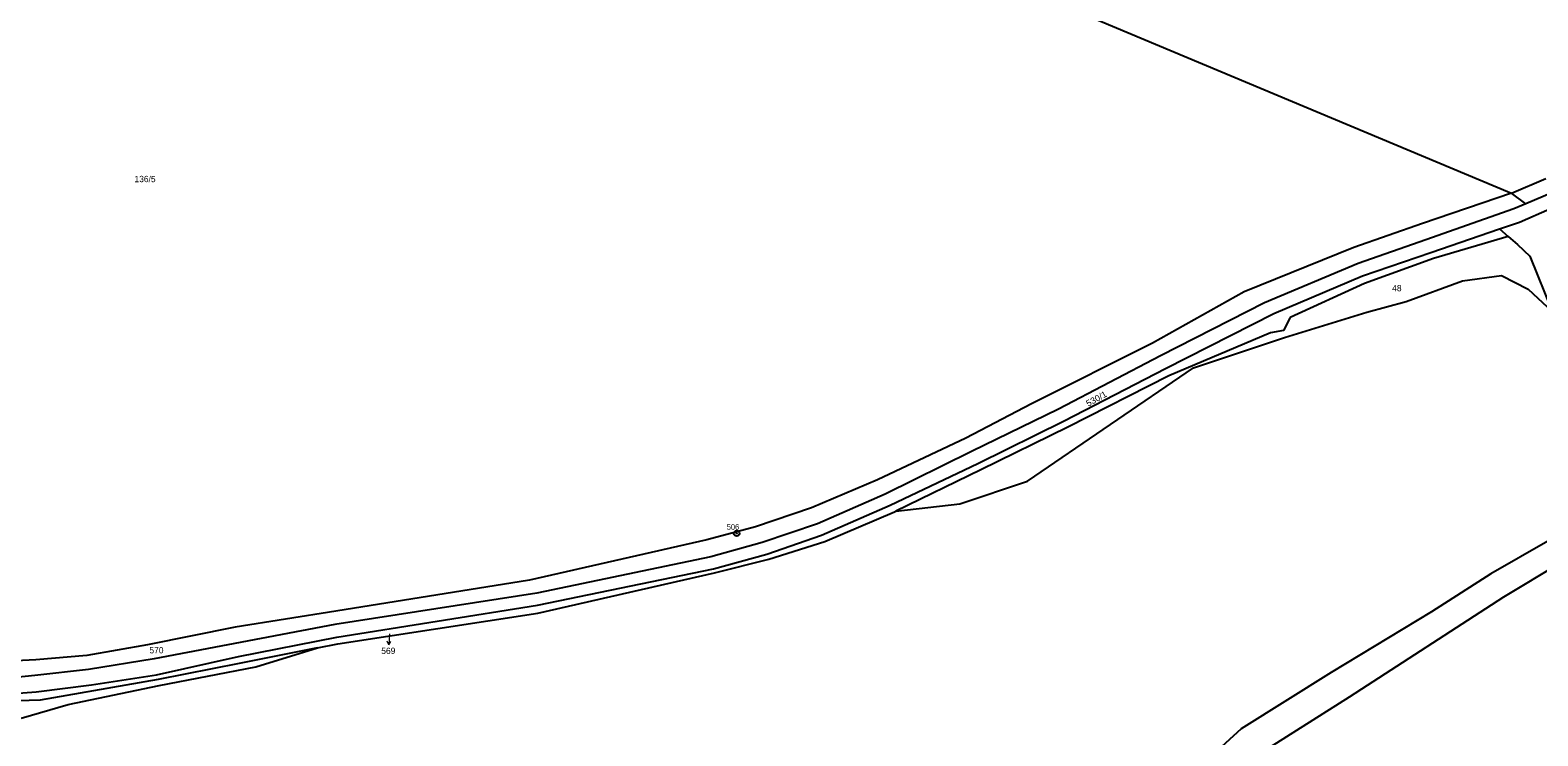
# Model space of a CAD drawing. Extents: x -885985 to -883535, y -1030025 to -1027941.
# Drawn here: x -885401.2 to -884995.2, y -1028874.7 to -1028684.8 of the extents above; entities that cross this region are included whole.
import ezdxf
from ezdxf.enums import TextEntityAlignment as Align

# ---------------------------------------------------------------- set-up
doc = ezdxf.new("R2010")
doc.units = 0
doc.header["$LTSCALE"] = 0.68
for name, color, linetype, lineweight in [('1', 7, 'Continuous', 25), ('7', 7, 'Continuous', 13), ('8', 7, 'Continuous', 25)]:
    doc.layers.add(name, color=color, linetype=linetype, lineweight=lineweight)
doc.layers.add('2', color=7, linetype='Continuous')

msp = doc.modelspace()

# ---------------------------------------------------------------- linework, layer by layer
at = {"layer": '1'}
for p, q in [((-885150.37, -1028666.64), (-885002.27, -1028728.64)), ((-885002.27, -1028728.64), (-884993.01, -1028724.72)), ((-884989.08, -1028727.59), (-884998.46, -1028731.48)), ((-885002.27, -1028728.64), (-885026.25, -1028736.76)), ((-884998.46, -1028731.48), (-885002.27, -1028728.64)), ((-884998.46, -1028731.48), (-885001.68, -1028732.81)), ((-885001.68, -1028732.81), (-885025.39, -1028741.17)), ((-885000.12, -1028736.41), (-884991.94, -1028732.85)), ((-885026.25, -1028736.76), (-885044.71, -1028743.24)), ((-885024, -1028744.64), (-885005.53, -1028738.28)), ((-885005.53, -1028738.28), (-885000.12, -1028736.41)), ((-885005.53, -1028738.28), (-885003.15, -1028740.31)), ((-885044.71, -1028743.24), (-885074.31, -1028755.16)), ((-885025.39, -1028741.17), (-885043.55, -1028747.61)), ((-885003.15, -1028740.31), (-885023.28, -1028746.26)), ((-885003.15, -1028740.31), (-885000.66, -1028742.44)), ((-885000.66, -1028742.44), (-884997.39, -1028745.58)), ((-885043.55, -1028747.61), (-885068.77, -1028758.15)), ((-885042.41, -1028750.88), (-885024, -1028744.64)), ((-885023.28, -1028746.26), (-885041.91, -1028752.92)), ((-884997.39, -1028745.58), (-884991.36, -1028760.48)), ((-885066.31, -1028761.01), (-885042.41, -1028750.88)), ((-885030.7, -1028757.8), (-885015.49, -1028752.21)), ((-885015.49, -1028752.21), (-885005.02, -1028750.81)), ((-885005.02, -1028750.81), (-884997.83, -1028754.45)), ((-885074.31, -1028755.16), (-885098.92, -1028769.02)), ((-885041.91, -1028752.92), (-885061.89, -1028762.1)), ((-884997.83, -1028754.45), (-884991.36, -1028760.48)), ((-885068.77, -1028758.15), (-885096.81, -1028772.42)), ((-885041.29, -1028760.63), (-885030.7, -1028757.8)), ((-885095.42, -1028775.86), (-885066.31, -1028761.01)), ((-885061.89, -1028762.1), (-885063.65, -1028765.58)), ((-885063.46, -1028767.52), (-885041.29, -1028760.63)), ((-885067.2, -1028766.24), (-885094.52, -1028777.83)), ((-885087.91, -1028775.64), (-885063.46, -1028767.52)), ((-885063.65, -1028765.58), (-885067.2, -1028766.24)), ((-885098.92, -1028769.02), (-885131.56, -1028785.34)), ((-885096.81, -1028772.42), (-885124.23, -1028786.82)), ((-885132.64, -1028806.18), (-885087.91, -1028775.64)), ((-885122.73, -1028789.96), (-885095.42, -1028775.86)), ((-885094.52, -1028777.83), (-885121.8, -1028791.6)), ((-885131.56, -1028785.34), (-885149.22, -1028794.57)), ((-885124.23, -1028786.82), (-885147.72, -1028798.18)), ((-885145.98, -1028801.41), (-885122.73, -1028789.96)), ((-885121.8, -1028791.6), (-885145.17, -1028803.1)), ((-885149.22, -1028794.57), (-885173.02, -1028805.81)), ((-885147.72, -1028798.18), (-885170.95, -1028809.66)), ((-885169.57, -1028812.59), (-885145.98, -1028801.41)), ((-885145.17, -1028803.1), (-885168.08, -1028814.2)), ((-885173.02, -1028805.81), (-885190.78, -1028813.33)), ((-885150.86, -1028812.24), (-885132.64, -1028806.18)), ((-885170.95, -1028809.66), (-885189.17, -1028817.62)), ((-885188.06, -1028820.74), (-885169.57, -1028812.59)), ((-885168.08, -1028814.2), (-885150.86, -1028812.24)), ((-885190.78, -1028813.33), (-885205.88, -1028818.43)), ((-885187.18, -1028822.42), (-885168.45, -1028814.38)), ((-885168.45, -1028814.38), (-885168.08, -1028814.2)), ((-885205.88, -1028818.43), (-885218.96, -1028821.95)), ((-885189.17, -1028817.62), (-885204.03, -1028822.68)), ((-885202.83, -1028825.83), (-885188.06, -1028820.74)), ((-885218.96, -1028821.95), (-885266.75, -1028832.84)), ((-885204.03, -1028822.68), (-885217.93, -1028826.52)), ((-885202.31, -1028827.13), (-885187.18, -1028822.42)), ((-884992.48, -1028822.32), (-885007.88, -1028831.14)), ((-885217.93, -1028826.52), (-885264.75, -1028836.35)), ((-885217.16, -1028829.74), (-885202.83, -1028825.83)), ((-885216.94, -1028830.86), (-885202.31, -1028827.13)), ((-885004.33, -1028837.31), (-884989.27, -1028828.21)), ((-885266.75, -1028832.84), (-885318.82, -1028841.18)), ((-885264.55, -1028839.57), (-885217.16, -1028829.74)), ((-885264.47, -1028841.68), (-885216.94, -1028830.86)), ((-885007.88, -1028831.14), (-885023.82, -1028841.37)), ((-885264.75, -1028836.35), (-885319.16, -1028844.75)), ((-885045.93, -1028864.26), (-885004.33, -1028837.31)), ((-885318.82, -1028841.18), (-885345.98, -1028845.43)), ((-885318.57, -1028848.17), (-885264.55, -1028839.57)), ((-885023.82, -1028841.37), (-885050.82, -1028857.65)), ((-885345.98, -1028845.43), (-885369.53, -1028850.23)), ((-885319.16, -1028844.75), (-885367.8, -1028854.02)), ((-885318.28, -1028849.92), (-885264.47, -1028841.68)), ((-885345.1, -1028853.37), (-885318.57, -1028848.17)), ((-885385.93, -1028853.05), (-885399.64, -1028854.25)), ((-885369.53, -1028850.23), (-885385.93, -1028853.05)), ((-885367.13, -1028858.28), (-885345.1, -1028853.37)), ((-885323.77, -1028851.05), (-885344.88, -1028855.25)), ((-885340.44, -1028856.18), (-885323.77, -1028851.05)), ((-885323.77, -1028851.05), (-885318.28, -1028849.92)), ((-885399.64, -1028854.25), (-885410.62, -1028854.82)), ((-885385.46, -1028856.84), (-885399.89, -1028858.44)), ((-885367.8, -1028854.02), (-885385.46, -1028856.84)), ((-885344.88, -1028855.25), (-885366.69, -1028859.51)), ((-885366.45, -1028861.16), (-885340.44, -1028856.18)), ((-885050.82, -1028857.65), (-885075.09, -1028872.83)), ((-885399.89, -1028858.44), (-885410.76, -1028859.59)), ((-885399.54, -1028862.89), (-885384.63, -1028860.95)), ((-885390.91, -1028866.26), (-885366.45, -1028861.16)), ((-885384.63, -1028860.95), (-885367.13, -1028858.28)), ((-885366.69, -1028859.51), (-885384.14, -1028862.64)), ((-885398.51, -1028865.1), (-885410.58, -1028865.49)), ((-885410.55, -1028863.73), (-885399.54, -1028862.89)), ((-885384.14, -1028862.64), (-885398.51, -1028865.1)), ((-885069.87, -1028879.41), (-885045.93, -1028864.26)), ((-885403.56, -1028869.98), (-885390.91, -1028866.26)), ((-885075.09, -1028872.83), (-885083.5, -1028880.56))]:
    msp.add_line(p, q, dxfattribs=at)
at = {"layer": '7'}
msp.add_line((-885304.599, -1028850.254), (-885304.03, -1028849.29), dxfattribs=at)
msp.add_lwpolyline([(-885304.39, -1028847.26), (-885304.599, -1028850.254), (-885305.029, -1028849.22)], dxfattribs=at)
at = {"layer": '8'}
for radius in [0.75, 0.03]:
    msp.add_circle((-885210.93, -1028820.2198), radius, dxfattribs=at)

# ---------------------------------------------------------------- texts
at = {"layer": '2'}
for s, p in [('136/5', (-885373.08, -1028725.675)), ('48', (-885034.42, -1028755.045)), ('570', (-885369.05, -1028852.525))]:
    msp.add_text(s, height=1.7, dxfattribs=at).set_placement(p)
at = {"layer": '2', "width": 1.05}
msp.add_text('530/1', height=1.7, rotation=29, dxfattribs=at).set_placement((-885116.273, -1028786.161))
at = {"layer": '2'}
msp.add_text('569', height=1.7, dxfattribs=at).set_placement((-885304.729, -1028852.685), align=Align.CENTER)
at = {"layer": '8'}
msp.add_text('506', height=1.5, dxfattribs=at).set_placement((-885210.251, -1028819.232), align=Align.RIGHT)

doc.saveas('drawing.dxf')
